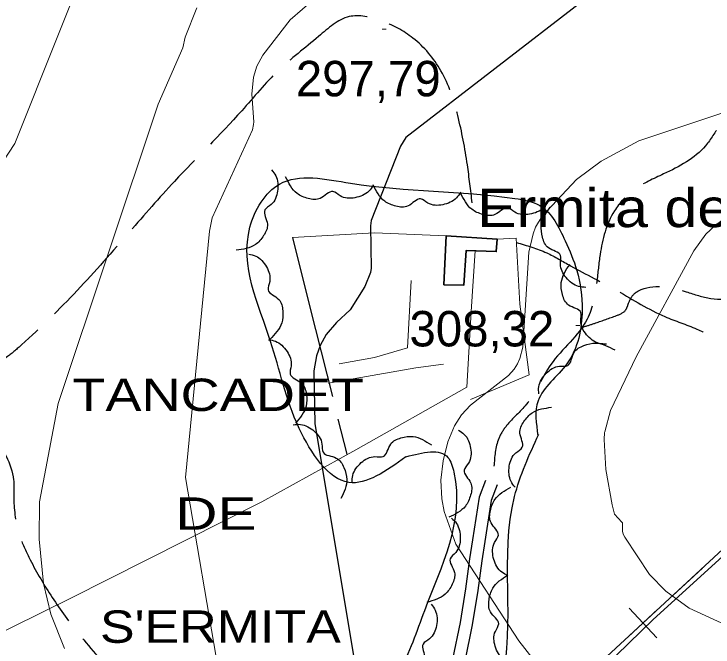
# Model space of a CAD drawing. Extents: x 480269 to 484877, y 4383588 to 4386804.
# Drawn here: x 483816.1 to 483988.8, y 4385627.3 to 4385783.6 of the extents above; entities that cross this region are included whole.
import ezdxf

# ---------------------------------------------------------------- set-up
doc = ezdxf.new("R2010")
doc.units = 0
doc.header["$LTSCALE"] = 3.8
doc.linetypes.add('LONG_DASHED', pattern=[7.5, 6, -1.5])
for name, color, linetype, lineweight in [('25', 7, 'LONG_DASHED', 25), ('27', 7, 'Continuous', 25), ('34', 7, 'Continuous', 35), ('38', 7, 'Continuous', 25), ('47', 7, 'Continuous', 35), ('51', 7, 'Continuous', 13), ('7', 7, 'Continuous', 13), ('8', 7, 'Continuous', 25), ('9', 7, 'Continuous', 13)]:
    doc.layers.add(name, color=color, linetype=linetype, lineweight=lineweight)
doc.layers.add('5', color=7, linetype='Continuous')

msp = doc.modelspace()

# ---------------------------------------------------------------- linework, layer by layer
at = {"layer": '25'}
msp.add_lwpolyline([(483884.92, 4385728.41), (483889.17, 4385711.26), (483898.31, 4385674.91)], dxfattribs=at)
at = {"layer": '27'}
for points in [[(483879.72, 4385745.13), (483880.75, 4385743.69), (483881.21, 4385739.92), (483879.62, 4385736.59), (483878.08, 4385735.24), (483878.69, 4385731.74), (483877.76, 4385728.9), (483875.71, 4385726.68), (483870.95, 4385725.28)], [(483912.9, 4385674.29), (483898.77, 4385667.96), (483886.57, 4385681.27), (483879.47, 4385702.8), (483874.37, 4385730.98), (483881.69, 4385741.64), (483899.21, 4385741.86), (483939.8, 4385738.09), (483946.02, 4385736.31), (483952.23, 4385727.66), (483955.11, 4385720.33), (483956.44, 4385710.57), (483952.67, 4385697.25), (483945.57, 4385688.15), (483945.51, 4385679.45)], [(483904.79, 4385741.32), (483903.75, 4385739.88), (483900.32, 4385738.27), (483896.65, 4385738.73), (483894.89, 4385739.78), (483891.75, 4385738.1), (483888.77, 4385738.09), (483886.01, 4385739.34), (483883.19, 4385743.42)], [(483926.42, 4385739.67), (483925.4, 4385738.22), (483921.99, 4385736.54), (483918.32, 4385736.95), (483916.54, 4385737.97), (483913.43, 4385736.24), (483910.45, 4385736.18), (483907.67, 4385737.39), (483904.79, 4385741.42)], [(483947.97, 4385737.23), (483946.92, 4385735.8), (483943.47, 4385734.21), (483939.81, 4385734.71), (483938.06, 4385735.77), (483934.91, 4385734.12), (483931.92, 4385734.13), (483929.18, 4385735.41), (483926.39, 4385739.51)], [(483957.35, 4385716.13), (483955.58, 4385716.33), (483952.49, 4385718.53), (483951.09, 4385721.94), (483951.13, 4385724), (483948.13, 4385725.9), (483946.65, 4385728.5), (483946.39, 4385731.51), (483948.55, 4385735.97)], [(483874.09, 4385724.37), (483875.79, 4385723.87), (483878.46, 4385721.18), (483879.25, 4385717.57), (483878.85, 4385715.55), (483881.48, 4385713.16), (483882.49, 4385710.35), (483882.23, 4385707.34), (483879.33, 4385703.32)], [(483962.42, 4385702.11), (483960.65, 4385702.29), (483957.53, 4385704.44), (483956.09, 4385707.85), (483956.11, 4385709.9), (483953.09, 4385711.77), (483951.58, 4385714.35), (483951.28, 4385717.35), (483953.39, 4385721.84)], [(483878.95, 4385703.21), (483880.68, 4385702.83), (483883.53, 4385700.32), (483884.56, 4385696.78), (483884.31, 4385694.74), (483887.1, 4385692.53), (483888.3, 4385689.8), (483888.25, 4385686.78), (483885.63, 4385682.57)], [(483945.73, 4385689.82), (483945.74, 4385691.6), (483947.59, 4385694.91), (483950.83, 4385696.66), (483952.88, 4385696.84), (483954.45, 4385700.03), (483956.87, 4385701.78), (483959.84, 4385702.37), (483964.51, 4385700.69)], [(483939.88, 4385666.78), (483938.87, 4385668.23), (483938.45, 4385672), (483940.08, 4385675.31), (483941.64, 4385676.65), (483941.08, 4385680.16), (483942.04, 4385682.98), (483944.12, 4385685.18), (483948.89, 4385686.52)], [(483885.09, 4385682.22), (483886.86, 4385682.29), (483890.26, 4385680.6), (483892.17, 4385677.45), (483892.45, 4385675.41), (483895.71, 4385673.99), (483897.58, 4385671.66), (483898.3, 4385668.73), (483896.86, 4385663.98)], [(483925.91, 4385680.91), (483927.33, 4385679.84), (483928.9, 4385676.39), (483928.37, 4385672.73), (483927.3, 4385670.98), (483928.93, 4385667.82), (483928.89, 4385664.83), (483927.6, 4385662.1), (483923.47, 4385659.35)], [(483603.65, 4385366.99), (483624.2, 4385382.47), (483632.03, 4385398.91), (483636.72, 4385422.41), (483645.34, 4385439.65), (483660.21, 4385444.35), (483671.96, 4385455.31), (483662.56, 4385467.06), (483659.43, 4385476.46), (483674.31, 4385492.91), (483694.66, 4385499.96), (483704.06, 4385490.56), (483711.11, 4385468.63), (483722.85, 4385451.4), (483736.16, 4385456.1), (483742.42, 4385467.85), (483748.69, 4385484.3), (483759.65, 4385490.56), (483776.88, 4385484.3), (483802.71, 4385469.41), (483826.99, 4385463.15), (483860.65, 4385463.15), (483873.96, 4385476.46), (483902.15, 4385486.65), (483911.55, 4385506.23), (483932.69, 4385513.28), (483942.86, 4385514.85), (483932.69, 4385531.3), (483915.46, 4385547.75), (483903.72, 4385547.75), (483886.49, 4385539.13), (483871.61, 4385529.73), (483863.78, 4385533.65), (483865.35, 4385544.61), (483871.61, 4385560.28), (483873.96, 4385572.03), (483874.75, 4385588.48), (483884.93, 4385596.31), (483910.76, 4385592.4), (483924.07, 4385597.1), (483936.6, 4385618.25), (483939.73, 4385664.46), (483945.7, 4385679.85)], [(483899.62, 4385667.93), (483899.78, 4385669.7), (483901.88, 4385672.85), (483905.26, 4385674.34), (483907.31, 4385674.36), (483909.14, 4385677.41), (483911.69, 4385678.96), (483914.69, 4385679.3), (483919.21, 4385677.26)], [(483912.9, 4385674.29), (483923.29, 4385674.14), (483924.74, 4385670.49), (483917.46, 4385636.27), (483910.91, 4385620.98), (483903.63, 4385613.69), (483870.52, 4385620.98), (483865.42, 4385617.33), (483855.23, 4385603.13), (483849.77, 4385575.46), (483837.4, 4385560.17), (483824.66, 4385553.25), (483810.1, 4385539.78), (483808.28, 4385524.12), (483815.56, 4385511.01), (483824.66, 4385503.37), (483824.3, 4385494.63), (483788.99, 4385500.09), (483765.34, 4385521.94), (483747.51, 4385543.78), (483724.94, 4385566.72), (483711.84, 4385571.46), (483688.55, 4385568.54), (483677.76, 4385562.31)], [(484014.05, 4385670.81), (484017.39, 4385650.28), (484020.24, 4385642.5), (484014.83, 4385637.55), (484001.64, 4385631.76), (483990.04, 4385622.38), (483980.75, 4385616.58), (483970.02, 4385621.89), (483958.86, 4385618.42), (483947.32, 4385610.24), (483933.72, 4385597.95), (483930.76, 4385592.92), (483919.05, 4385578.54), (483912.63, 4385572.04), (483908.46, 4385567.92), (483914.89, 4385559.41), (483924.68, 4385551.72), (483937.96, 4385539.35), (483944.69, 4385532.85), (483966.32, 4385509.19), (483974.91, 4385515.31), (483977.92, 4385521.23), (483994.4, 4385530.63), (484007.6, 4385531.97), (484021.37, 4385536.44), (484029.11, 4385538.18), (484047.22, 4385540.8), (484070.47, 4385552.42), (484079.53, 4385562.09), (484076.79, 4385566.86), (484070.36, 4385568.5), (484062.68, 4385577.53), (484051.76, 4385589.44), (484040.2, 4385597.58), (484047.99, 4385607.39), (484060.56, 4385618.17), (484074.87, 4385630.55), (484092.34, 4385642.26), (484103.02, 4385648.27), (484103.77, 4385648.09)], [(483937.76, 4385645.12), (483936.27, 4385646.09), (483934.5, 4385649.44), (483934.79, 4385653.12), (483935.75, 4385654.94), (483933.93, 4385657.99), (483933.77, 4385660.97), (483934.89, 4385663.78), (483938.83, 4385666.79)], [(483924.19, 4385659.15), (483925.4, 4385657.86), (483926.34, 4385654.18), (483925.2, 4385650.67), (483923.84, 4385649.13), (483924.89, 4385645.74), (483924.34, 4385642.81), (483922.6, 4385640.34), (483918.06, 4385638.34)], [(483938.53, 4385623.42), (483936.98, 4385624.29), (483934.97, 4385627.5), (483935, 4385631.19), (483935.83, 4385633.07), (483933.8, 4385635.99), (483933.44, 4385638.95), (483934.35, 4385641.83), (483938.08, 4385645.11)], [(483919.17, 4385637.88), (483920.15, 4385636.39), (483920.46, 4385632.61), (483918.74, 4385629.35), (483917.14, 4385628.06), (483917.61, 4385624.53), (483916.58, 4385621.73), (483914.44, 4385619.59), (483909.63, 4385618.38)]]:
    msp.add_spline(points, degree=3, dxfattribs=at)
at = {"layer": '34'}
for p, q in [((483986.15, 4385646.82), (483978.81, 4385640.03)), ((483975.14, 4385636.64), (483967.8, 4385629.85)), ((483968.07, 4385636.91), (483974.86, 4385629.57))]:
    msp.add_line(p, q, dxfattribs=at)
msp.add_lwpolyline([(483872.5, 4386448.65), (483868, 4386266), (483874, 4385990), (483911, 4385821), (484074, 4385832), (484088, 4385741), (483902, 4385569), (484007, 4385465), (484103, 4385395), (484103.22, 4385394.84)], dxfattribs=at)
at = {"layer": '38'}
for points in [[(483932.59, 4385668.47), (483931.03, 4385664.32), (483929.36, 4385653.83), (483928.64, 4385649.07), (483927.64, 4385641.72), (483926.27, 4385633.35), (483924.42, 4385624.31)], [(483935.43, 4385667.4), (483933.98, 4385663.54), (483932.36, 4385653.37), (483931.65, 4385648.64), (483930.64, 4385641.27), (483929.26, 4385632.8), (483927.42, 4385623.81)]]:
    msp.add_lwpolyline(points, dxfattribs=at)
at = {"layer": '38', "linetype": 'LONG_DASHED'}
for points in [[(483929.28, 4385736.99), (483928.08, 4385746.4), (483925.72, 4385758.55), (483921.56, 4385769.63), (483914.64, 4385777.69), (483906.73, 4385781.98), (483898.88, 4385782.98), (483891.35, 4385778.12), (483881.4, 4385769.67), (483872.35, 4385759.74), (483855.72, 4385742.3), (483844.66, 4385729.87), (483831.67, 4385715.35), (483817.97, 4385701.95), (483814.49, 4385699.03), (483802.7, 4385691.38), (483794.92, 4385681.79), (483787.95, 4385667.75), (483779.25, 4385659.35), (483767.77, 4385659.76), (483758.57, 4385666.85), (483751.6, 4385677.77), (483748.29, 4385679.1), (483738.58, 4385686.7), (483737.97, 4385696.12), (483737.8, 4385699.37), (483731.47, 4385700.49), (483725.86, 4385702.35), (483721.6, 4385713.91), (483709.08, 4385719.37), (483703.66, 4385721.58), (483682.28, 4385706.24), (483675.96, 4385702.72), (483668.77, 4385703.21), (483656.94, 4385714.23), (483648.66, 4385720.84)], [(484040.63, 4385769.12), (484024.65, 4385771.88), (484015.68, 4385771.47), (484003.16, 4385767.34), (483994.39, 4385759.84), (483990.59, 4385756.14), (483986.92, 4385751.1), (483976.57, 4385744.13), (483969.34, 4385740.28), (483964.42, 4385735.01), (483960.88, 4385724.28), (483960.05, 4385717.48), (483957.69, 4385708.29), (483948.71, 4385697.1), (483942.64, 4385687.2), (483937.78, 4385682), (483935.83, 4385678.79), (483934.66, 4385671.95)], [(483956.5, 4385706.28), (483959.48, 4385707.24), (483964.6, 4385709.05), (483967.16, 4385710.51), (483967.84, 4385712.01), (483969.43, 4385714.65), (483970.39, 4385715.28), (483982.13, 4385715.04), (483988.21, 4385713.38), (484001.87, 4385715.45), (484018.56, 4385722.61), (484023.78, 4385726.51), (484029.13, 4385730.12), (484032.42, 4385729.52), (484038.39, 4385731.11), (484040.76, 4385733.94), (484050.39, 4385747.33), (484052.15, 4385755.09), (484047.89, 4385760.41), (484040.63, 4385769.12)], [(483940.2, 4385727.2), (483947.68, 4385724.65), (483953.56, 4385721.46), (483965.23, 4385715.24), (483976.86, 4385708.91), (483984.8, 4385705.82), (483990.76, 4385702.96), (484001.09, 4385700.32), (484009.35, 4385699.53), (484020.23, 4385697.91)], [(483553.1, 4385558.04), (483560, 4385565.85), (483569.77, 4385570.8), (483577.16, 4385573.63), (483588.52, 4385574.9), (483606.53, 4385575.01), (483613.6, 4385575.34), (483621.08, 4385584.92), (483634.19, 4385600.86), (483645.77, 4385609.97), (483659.79, 4385616.6), (483667.57, 4385620.28), (483678.63, 4385624.9), (483689.28, 4385631.34), (483694.37, 4385636.14), (483695.55, 4385637.52), (483703.2, 4385641.14), (483713.48, 4385650.23), (483722.91, 4385663.28), (483730.98, 4385671.49), (483737.59, 4385678.35), (483745.67, 4385681.84), (483752.15, 4385685.91), (483758.36, 4385690.52), (483768.54, 4385697.31), (483775.64, 4385697.41), (483781.1, 4385695.52), (483798.4, 4385686.78), (483802.9, 4385685.22), (483810.56, 4385679.57), (483815.98, 4385668.59), (483816.07, 4385663.36), (483817.61, 4385654.53), (483820.08, 4385648.86), (483825.53, 4385639.54), (483832.15, 4385630.46), (483841.58, 4385619.39), (483852.28, 4385607.67), (483862.9, 4385601.96)]]:
    msp.add_spline(points, degree=3, dxfattribs=at)
at = {"layer": '47'}
msp.add_lwpolyline([(483922.25, 4385716.74), (483922.85, 4385728.88), (483935.43, 4385728), (483935.23, 4385724.98), (483927.76, 4385725.23), (483927.2, 4385716.65)], close=True, dxfattribs=at)
at = {"layer": '51'}
for points in [[(483909.24, 4385561.99), (483904.57, 4385566.6), (483973.98, 4385634.15), (484016.42, 4385672.68), (484080.56, 4385727.17), (484073.87, 4385763.36)], [(483922.85, 4385728.88), (483905.14, 4385729.62), (483884.92, 4385728.41)], [(483928.89, 4385688.48), (483943.35, 4385694.52), (483941.03, 4385711.96), (483940.13, 4385728.27), (483935.43, 4385728)], [(483930.04, 4385725.15), (483929, 4385710.2), (483927.92, 4385691.51), (483900.55, 4385675.99)], [(483914.24, 4385717.8), (483913.27, 4385701.17), (483905.16, 4385698.8), (483896.43, 4385697.21)], [(483893.76, 4385692.45), (483915.33, 4385696.27), (483922.2, 4385697.19)], [(483900.55, 4385675.99), (483877.35, 4385663.15), (483830.13, 4385639.39)], [(483830.13, 4385639.39), (483771.6, 4385610.46), (483713.01, 4385576.64), (483639.54, 4385537.55)]]:
    msp.add_lwpolyline(points, dxfattribs=at)
at = {"layer": '7'}
for p, q in [((483907.04, 4385779.9), (483908.04, 4385779.9)), ((483954.88, 4385706.74), (483955.88, 4385706.74))]:
    msp.add_line(p, q, dxfattribs=at)
at = {"layer": '8'}
msp.add_lwpolyline([(483956.84, 4385787.06), (483912.92, 4385753.12), (483911.57, 4385751), (483904.35, 4385732.62), (483904.19, 4385731.31), (483904.28, 4385720.81), (483904.14, 4385719.85), (483904.14, 4385719.83), (483902.79, 4385716.31), (483899.12, 4385710.59), (483895.77, 4385707.45), (483893.23, 4385704.46), (483891.7, 4385701.81), (483890.81, 4385699.24), (483890.19, 4385695.53), (483890.42, 4385682.43), (483901.99, 4385612.92)], dxfattribs=at)
at = {"layer": '9'}
for points in [[(483848.01, 4385831.08), (483816.29, 4385751.63), (483813.34, 4385747.1)], [(483866.6, 4385621.42), (483858.49, 4385669.22), (483864.37, 4385730), (483865.07, 4385733.3), (483874.98, 4385755.01), (483875.29, 4385756.34), (483875.37, 4385757.03), (483874.82, 4385763.85), (483875.26, 4385768), (483876.08, 4385770.77), (483877.53, 4385773.46), (483884.33, 4385782.17), (483890.38, 4385787.56)], [(483861.29, 4385785.17), (483858.34, 4385777.89), (483857.82, 4385775.26), (483851.67, 4385761.39), (483826.97, 4385687.43), (483822.36, 4385663.15), (483822.3, 4385653.94), (483823.37, 4385642.97), (483825.19, 4385635.4), (483828.53, 4385626.97)], [(484104.06, 4385780.33), (484101.08, 4385778.98), (484055.59, 4385749.27), (484021.24, 4385738.89), (484009.23, 4385735.14), (483994.59, 4385734.13), (483993.52, 4385733.89), (483990.98, 4385732.61), (483989.39, 4385731.5), (483987.03, 4385729.3), (483984.02, 4385725.16), (483969.75, 4385699.01), (483963.44, 4385685.7), (483962.04, 4385680.47), (483961.99, 4385680.3), (483961.87, 4385678.59), (483962.27, 4385671.13), (483963.83, 4385662.4), (483964.46, 4385660.15), (483966.23, 4385658.12)], [(483991.65, 4385759.36), (483970.43, 4385752.32), (483961.17, 4385747.32), (483955.06, 4385742.77), (483946.56, 4385733.7), (483944.95, 4385731), (483944.31, 4385729.37), (483943.28, 4385724.81), (483941.82, 4385701.37), (483941.01, 4385698.55), (483940.44, 4385697.28), (483939.65, 4385695.94), (483938.24, 4385694.41), (483928.87, 4385687.07), (483926.66, 4385684.69), (483924.89, 4385681.92), (483923.28, 4385677.96), (483922.07, 4385673.28), (483921.53, 4385668.49), (483921.78, 4385663.92), (483922.38, 4385660.79), (483925.21, 4385652.74), (483940.83, 4385628.87), (483946.39, 4385621.68)], [(483966.23, 4385658.12), (483966.32, 4385658.04), (483966.37, 4385657.99), (483966.38, 4385657.97), (483966.38, 4385657.95), (483966.41, 4385655.91), (483966.47, 4385655.55), (483966.67, 4385655.03), (483966.99, 4385654.45), (483973.1, 4385645.26), (483977.15, 4385641.11), (483982.88, 4385636.88), (484001.87, 4385628.2)]]:
    msp.add_lwpolyline(points, dxfattribs=at)

# ---------------------------------------------------------------- texts
at = {"layer": '5'}
for s, height, width, p in [('Ermita de Son Segu[', 9.5, 1.15, (483930.5, 4385731.01)), ('TANCADET ', 8, 1.25, (483830.5, 4385685.6)), (' DE ', 8, 1.35, (483851.9, 4385656.28)), (" S'ERMITA", 8, 1.2, (483833.76, 4385628.36))]:
    msp.add_text(s, height=height, dxfattribs=dict(at, width=width)).set_placement(p)
at = {"layer": '7'}
for s, p in [('297,79', (483885.71, 4385763.31)), ('308,32', (483913.78, 4385701.55))]:
    msp.add_text(s, height=8.75, dxfattribs=at).set_placement(p)

doc.saveas('drawing.dxf')
